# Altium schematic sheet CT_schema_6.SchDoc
size 278 x 170 mm
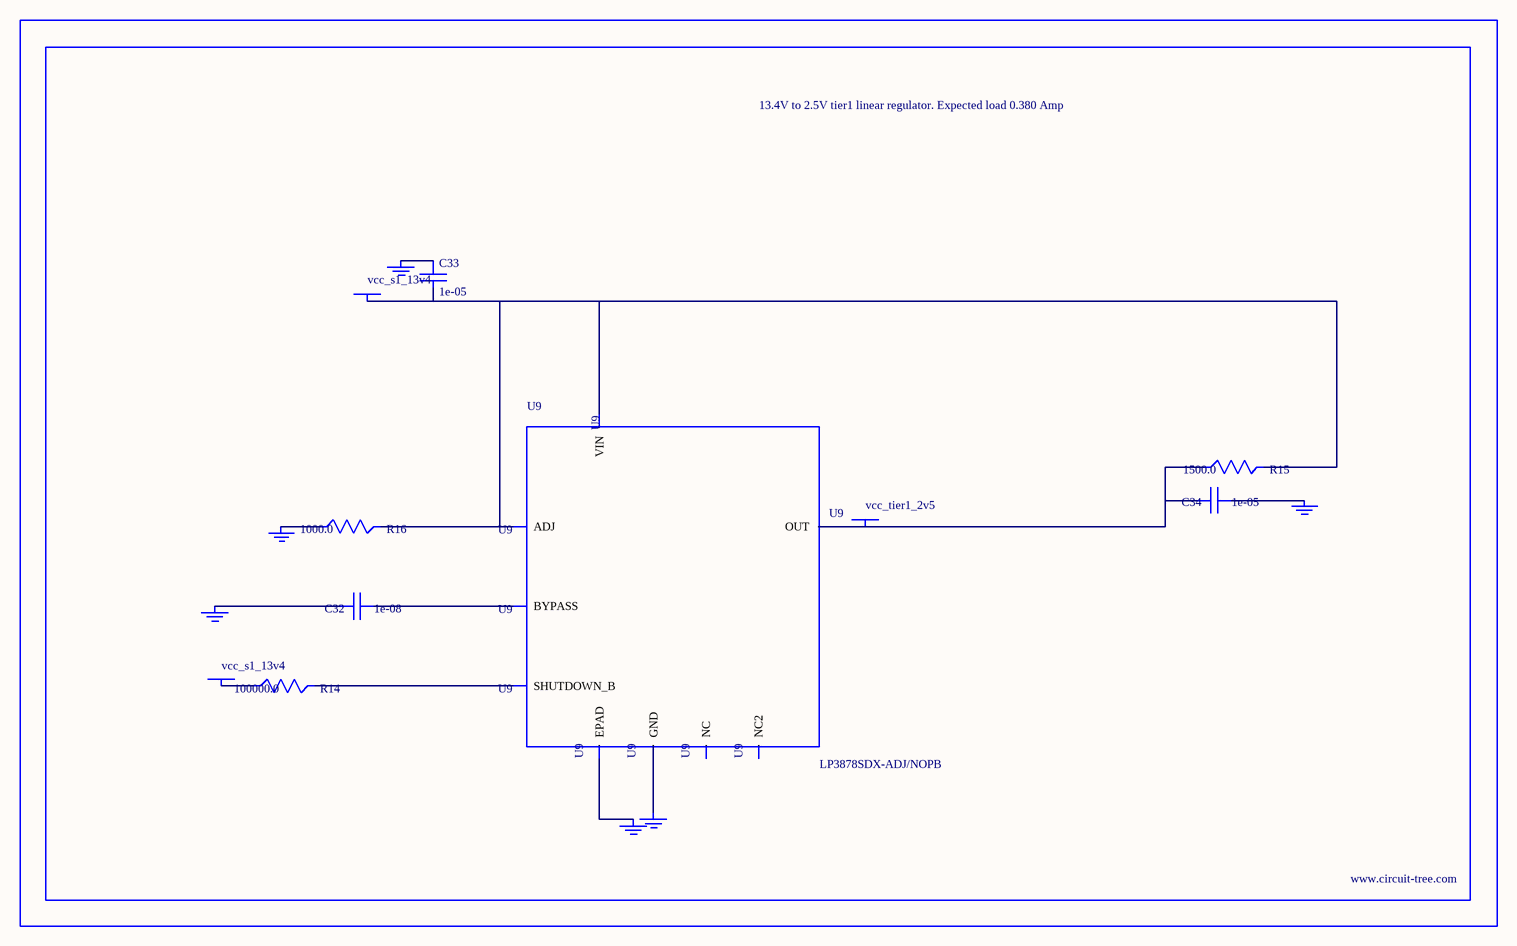
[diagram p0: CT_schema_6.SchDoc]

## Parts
BORDER5  (no value)
C32  1e-08  [C0402]
C33  1e-05  [C1210]
C34  1e-05  [C1210]
GND_INSTANCE_5_0  (no value)
GND_INSTANCE_5_1  (no value)
GND_INSTANCE_5_2  (no value)
GND_INSTANCE_5_3  (no value)
GND_INSTANCE_5_4  (no value)
GND_INSTANCE_5_5  (no value)
POWER_INSTANCE_5_0  vcc_s1_13v4
POWER_INSTANCE_5_1  vcc_s1_13v4
POWER_INSTANCE_5_2  vcc_tier1_2v5
R14  100000.0  [R0603]
R15  1500.0  [R0603]
R16  1000.0  [R0603]
U9  LP3878SDX-ADJ/NOPB  [WSON-8]

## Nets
NetC32_1: C32.1 U9.1(BYPASS)
NetC32_2: C32.2 GND_INSTANCE_5_0.0(GND)
NetC33_1: C33.1 GND_INSTANCE_5_1.0(GND)
NetC33_2: C33.2 POWER_INSTANCE_5_0.0(PWR) R15.2 R16.2 U9.4(VIN) U9.6(ADJ)
NetC34_1: C34.1 GND_INSTANCE_5_2.0(GND)
NetC34_2: C34.2 POWER_INSTANCE_5_2.0(PWR) R15.1 U9.5(OUT)
NetGND_INSTANCE_5_3_0: GND_INSTANCE_5_3.0(GND) R16.1
NetGND_INSTANCE_5_4_0: GND_INSTANCE_5_4.0(GND) U9.PAD(EPAD)
NetGND_INSTANCE_5_5_0: GND_INSTANCE_5_5.0(GND) U9.3(GND)
NetPOWER_INSTANCE_5_1_0: POWER_INSTANCE_5_1.0(PWR) R14.1
NetR14_2: R14.2 U9.8(SHUTDOWN_B)

Not connected (* = marked no-connect by the designer): U9 2(NC) 7(NC2)

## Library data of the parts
BORDER5 = BORDER_PAGE5
C32 = C0402C103K3RAC
C33 = C1210C106K5PACTU
C34 = GRM32DR61E106MA12L
GND_INSTANCE_5_0-GND_INSTANCE_5_5 = GND
POWER_INSTANCE_5_0-POWER_INSTANCE_5_2 = PWR
R14 = RC0603JR-07100KL
R15 = RC0603JR-071K5L
R16 = RC0603JR-071KL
